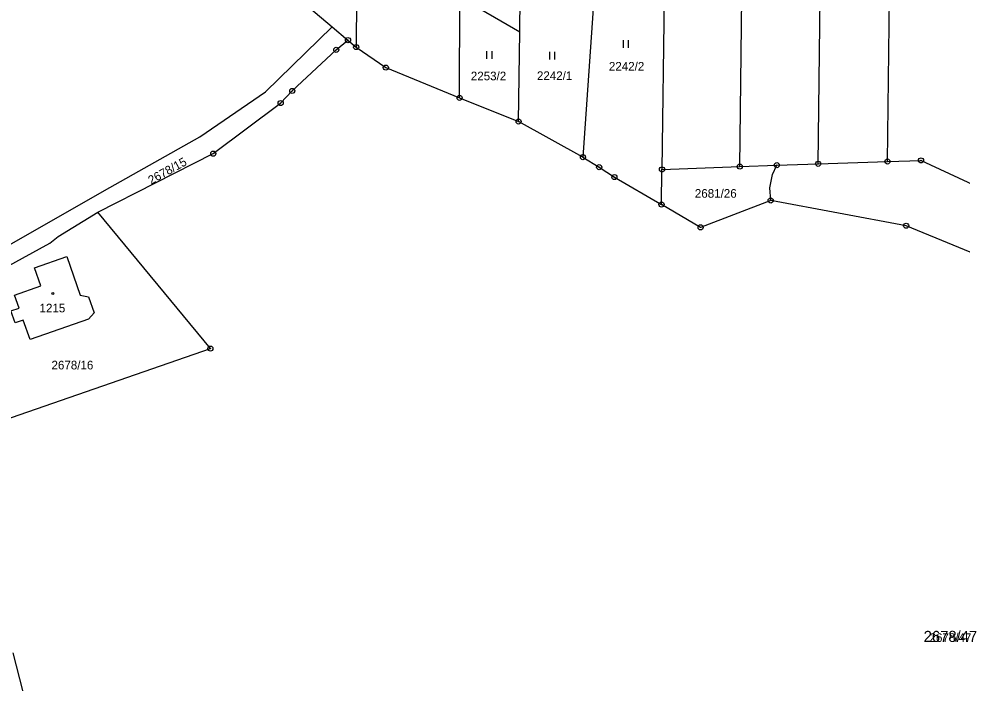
# Model space of a CAD drawing. Extents: x -758836 to -757729, y -1175316 to -1174366.
# Drawn here: x -758284.7 to -758099.5, y -1175013.2 to -1174882.8 of the extents above; entities that cross this region are included whole.
import ezdxf

# ---------------------------------------------------------------- set-up
doc = ezdxf.new("R2010")
doc.units = 0
for name, color, linetype in [('Hranice parcel', 7, 'Continuous'), ('Parcelní čísla', 7, 'Continuous'), ('Značky bodu BP', 7, 'Continuous'), ('Značky budov', 7, 'Continuous'), ('Značky kultur', 7, 'Continuous')]:
    doc.layers.add(name, color=color, linetype=linetype)

msp = doc.modelspace()

# ---------------------------------------------------------------- linework, layer by layer
at = {"layer": 'Hranice parcel'}
for p, q in [((-758114.13, -1174910.8), (-758112.36, -1174774.1)), ((-758143.14, -1174911.79), (-758141.37, -1174774.78)), ((-758127.73, -1174911.25), (-758125.97, -1174774.42)), ((-758218.18, -1174826.63), (-758218.45, -1174888.34)), ((-758157.87, -1174870.96), (-758158.4, -1174912.36)), ((-758186.32, -1174885.38), (-758186.22, -1174876.87)), ((-758198.15, -1174898.31), (-758198.12, -1174878.49)), ((-758198.12, -1174878.49), (-758186.32, -1174885.38)), ((-758171.87, -1174879.84), (-758173.93, -1174909.94)), ((-758223.14, -1174884.37), (-758220.06, -1174886.98)), ((-758220.06, -1174886.98), (-758218.45, -1174888.34)), ((-758186.55, -1174902.95), (-758186.32, -1174885.38)), ((-758198.15, -1174898.31), (-758186.55, -1174902.95)), ((-758173.93, -1174909.94), (-758186.55, -1174902.95)), ((-758127.73, -1174911.25), (-758114.13, -1174910.8)), ((-758158.49, -1174919.25), (-758158.4, -1174912.36)), ((-758158.4, -1174912.36), (-758143.14, -1174911.79)), ((-758143.14, -1174911.79), (-758135.88, -1174911.52)), ((-758135.88, -1174911.52), (-758127.73, -1174911.25)), ((-758280.48, -1175027.85), (-758285.8, -1175007.25))]:
    msp.add_line(p, q, dxfattribs=at)
for points in [[(-758238.89, -1174870.98), (-758232.33, -1174876.61), (-758223.14, -1174884.37)], [(-758302.92, -1174935.57), (-758286.99, -1174927.44), (-758267.9, -1174916.47), (-758249.14, -1174905.98), (-758236.24, -1174897.16), (-758223.14, -1174884.37)], [(-758269.21, -1174920.77), (-758246.51, -1174909.26), (-758233.28, -1174899.33), (-758231, -1174896.96), (-758222.36, -1174888.88), (-758220.06, -1174886.98)], [(-758218.45, -1174888.34), (-758212.63, -1174892.38), (-758198.15, -1174898.31)], [(-758173.93, -1174909.94), (-758170.73, -1174911.91), (-758167.75, -1174913.86), (-758158.49, -1174919.25)], [(-758114.13, -1174910.8), (-758107.54, -1174910.58), (-758080.03, -1174923.36), (-758076.9, -1174924.17)], [(-758137.06, -1174918.45), (-758137.2, -1174915.99), (-758136.71, -1174913.36), (-758135.88, -1174911.52)], [(-758137.06, -1174918.45), (-758150.82, -1174923.72), (-758158.49, -1174919.25)], [(-757919.47, -1174939.02), (-757939.8, -1174930.25), (-757949.26, -1174927.98), (-757957.21, -1174927.28), (-758013.54, -1174927.25), (-758023.59, -1174928.73), (-758047.8, -1174938.11), (-758063.96, -1174936.81), (-758089.79, -1174931.96), (-758110.46, -1174923.41), (-758137.06, -1174918.45)], [(-758297.41, -1174937.08), (-758278.62, -1174926.8), (-758276.96, -1174925.54), (-758269.21, -1174920.77)], [(-758296.01, -1174964.46), (-758247.07, -1174947.51), (-758269.21, -1174920.77)], [(-758271, -1174941.74), (-758282.48, -1174945.75), (-758283.82, -1174941.92), (-758285.42, -1174942.48), (-758286.25, -1174940.1), (-758284.66, -1174939.55), (-758285.55, -1174937), (-758280.36, -1174935.18), (-758281.59, -1174931.68), (-758275.27, -1174929.47), (-758272.62, -1174937.05), (-758271.01, -1174937.37), (-758269.92, -1174940.49), (-758271, -1174941.74)]]:
    msp.add_lwpolyline(points, dxfattribs=at)
at = {"layer": 'Značky bodu BP'}
for centre, radius in [((-758220.06, -1174886.98), 0.5), ((-758220.06, -1174886.98), 0.0303), ((-758222.36, -1174888.88), 0.5), ((-758222.36, -1174888.88), 0.0303), ((-758218.45, -1174888.34), 0.5), ((-758218.45, -1174888.34), 0.0303), ((-758212.63, -1174892.38), 0.5), ((-758212.63, -1174892.38), 0.0303), ((-758231, -1174896.96), 0.5), ((-758231, -1174896.96), 0.0303), ((-758198.15, -1174898.31), 0.5), ((-758198.15, -1174898.31), 0.0303), ((-758233.28, -1174899.33), 0.5), ((-758233.28, -1174899.33), 0.0303), ((-758186.55, -1174902.95), 0.5), ((-758186.55, -1174902.95), 0.0303), ((-758246.51, -1174909.26), 0.5), ((-758246.51, -1174909.26), 0.0303), ((-758173.93, -1174909.94), 0.5), ((-758173.93, -1174909.94), 0.0303), ((-758135.88, -1174911.52), 0.5), ((-758127.73, -1174911.25), 0.5), ((-758127.73, -1174911.25), 0.0303), ((-758114.13, -1174910.8), 0.5), ((-758114.13, -1174910.8), 0.0303), ((-758107.54, -1174910.58), 0.5), ((-758107.54, -1174910.58), 0.0303), ((-758170.73, -1174911.91), 0.5), ((-758170.73, -1174911.91), 0.0303), ((-758158.4, -1174912.36), 0.5), ((-758158.4, -1174912.36), 0.0303), ((-758143.14, -1174911.79), 0.5), ((-758143.14, -1174911.79), 0.0303), ((-758135.88, -1174911.52), 0.0303), ((-758167.75, -1174913.86), 0.5), ((-758167.75, -1174913.86), 0.0303), ((-758137.06, -1174918.45), 0.5), ((-758137.06, -1174918.45), 0.0303), ((-758158.49, -1174919.25), 0.5), ((-758158.49, -1174919.25), 0.0303), ((-758150.82, -1174923.72), 0.5), ((-758150.82, -1174923.72), 0.0303), ((-758110.46, -1174923.41), 0.5), ((-758110.46, -1174923.41), 0.0303), ((-758247.07, -1174947.51), 0.5), ((-758247.07, -1174947.51), 0.0303)]:
    msp.add_circle(centre, radius, dxfattribs=at)
at = {"layer": 'Značky budov'}
msp.add_circle((-758278.01, -1174936.7), 0.175, dxfattribs=at)
at = {"layer": 'Značky kultur'}
for p, q in [((-758165.95, -1174888.49), (-758165.95, -1174886.99)), ((-758164.95, -1174888.49), (-758164.95, -1174886.99)), ((-758192.77, -1174890.64), (-758192.77, -1174889.14)), ((-758191.77, -1174890.64), (-758191.77, -1174889.14)), ((-758180.43, -1174890.81), (-758180.43, -1174889.31)), ((-758179.43, -1174890.81), (-758179.43, -1174889.31))]:
    msp.add_line(p, q, dxfattribs=at)

# ---------------------------------------------------------------- texts
at = {"layer": 'Parcelní čísla'}
for s, height, p in [('2242/2', 1.7, (-758168.83, -1174892.97)), ('2253/2', 1.7, (-758195.94, -1174894.87)), ('2242/1', 1.7, (-758182.96, -1174894.81)), ('2681/26', 1.7, (-758151.95, -1174917.91)), ('1215', 1.7, (-758280.63, -1174940.41)), ('2678/16', 1.7, (-758278.28, -1174951.6)), ('2678/47', 2.175, (-758107.02, -1175005.08)), ('2678/47', 1.7, (-758105.86, -1175005.08))]:
    msp.add_text(s, height=height, dxfattribs=at).set_placement(p)
msp.add_text('2678/15', height=1.7, rotation=29, dxfattribs=at).set_placement((-758258.72, -1174915.36))

doc.saveas('drawing.dxf')
